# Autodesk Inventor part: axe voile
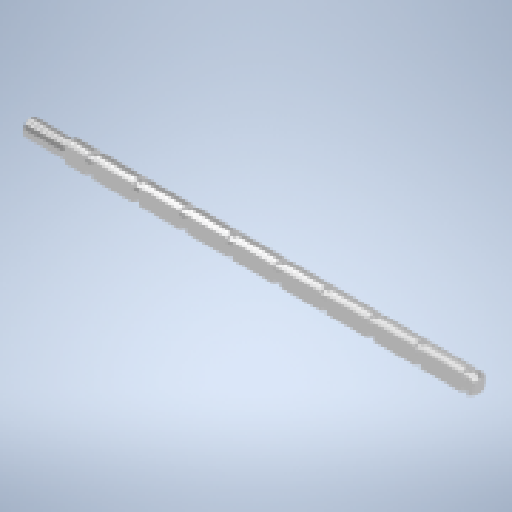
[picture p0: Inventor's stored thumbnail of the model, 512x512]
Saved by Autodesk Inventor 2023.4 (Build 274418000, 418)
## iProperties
Created: 2023-11
Part Number: axe voile
Material: Aluminium 6061
Document SubType Name: Modeling
Designer: mel
Density: 2.7 g/cm^3
Appearance: Aluminium - Plat
Author: mel
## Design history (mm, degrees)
sketch "Esquisse1"
  geometry: L1 (0, 0)-(200, 0); L2 (200, 0)-(200, 5); L3 (200, 5)-(0, 5); L4 (0, 5)-(0, 4); L5 (-20, 4)-(0, 4); L6 (0, 0)-(-20, 0); L7 (-20, 0)-(-20, 4); L8 (10, 5)-(13.1, 5); L9 (13.1, 5)-(13.1, 3.5); L10 (13.1, 3.5)-(10, 3.5); L11 (10, 3.5)-(10, 5); L12 (33, 5)-(36.1, 5); L13 (36.1, 5)-(36.1, 3.5); L14 (36.1, 3.5)-(33, 3.5); L15 (33, 3.5)-(33, 5); L16 (56, 5)-(59.1, 5); L17 (59.1, 5)-(59.1, 3.5); L18 (59.1, 3.5)-(56, 3.5); L19 (56, 3.5)-(56, 5); L20 (79, 5)-(82.1, 5); L21 (82.1, 5)-(82.1, 3.5); L22 (82.1, 3.5)-(79, 3.5); L23 (79, 3.5)-(79, 5); L24 (102, 5)-(105.1, 5); L25 (105.1, 5)-(105.1, 3.5); L26 (105.1, 3.5)-(102, 3.5); L27 (102, 3.5)-(102, 5); L28 (125, 5)-(128.1, 5); L29 (128.1, 5)-(128.1, 3.5); L30 (128.1, 3.5)-(125, 3.5); L31 (125, 3.5)-(125, 5); L32 (148, 5)-(151.1, 5); L33 (151.1, 5)-(151.1, 3.5); L34 (151.1, 3.5)-(148, 3.5); L35 (148, 3.5)-(148, 5); L36 (171, 5)-(174.1, 5); L37 (174.1, 5)-(174.1, 3.5); L38 (174.1, 3.5)-(171, 3.5); L39 (171, 3.5)-(171, 5); L40 (194, 5)-(197.1, 5); L41 (197.1, 5)-(197.1, 3.5); L42 (197.1, 3.5)-(194, 3.5); L43 (194, 3.5)-(194, 5); 17 further points
  constraints: 86 end point, 5 parallel, 4 horizontal, 2 perpendicular, 1 point on line, 64 other
  dimensions: "d0" = 200 distance of L3.end L2.end; "d1" = 5 distance of L2.end L1.end; "d2" = 4 distance between parallel lines of L6 L5; "d3" = 20 distance between parallel lines of L7 L4; "d4" = 3.1 distance between parallel lines of L9 L11; "d5" = 3.5 distance between parallel lines of L1 L10; "d6" = 10 distance between parallel lines of L11 L4; "d9" = 23 distance of L8.start L12.start
revolve "Révolution1" sketch "Esquisse1" stored, may be unused: angle "d14" = 90 deg
sketch "Esquisse2"
  geometry: L1 (-12.8, 10.795)-(-3, 10.795); L2 (-3, 10.795)-(-3, -12.633); L3 (-3, -12.633)-(-12.8, -12.633); L4 (-12.8, -12.633)-(-12.8, 10.795); 1 further point
  constraints: 8 end point, 2 parallel, 1 horizontal, 1 perpendicular
  dimensions: "d15" = 3 distance from line of L2 point (0, 0)
extrude "Extrusion1" cut sketch "Esquisse2" stored distance "d16" = 0; taper "d17" = 0 deg
chamfer "Chanfrein1" distance "d18" = 2; stored, may be unused: second distance "d19" = 2, angle "d20" = 45 deg
sketch "Esquisse3"
  geometry: 1 further point
hole "Perçage1" sketch "Esquisse3" at (0, 0) diameter "d21" = 3.242; stored, may be unused: countersink angle "d25" = 90 deg, drill point angle "d27" = 118 deg; dims "d22" = 20, "d23" = 19.05, "d24" = 4.775, "d26" = 25
node "Solide1"
